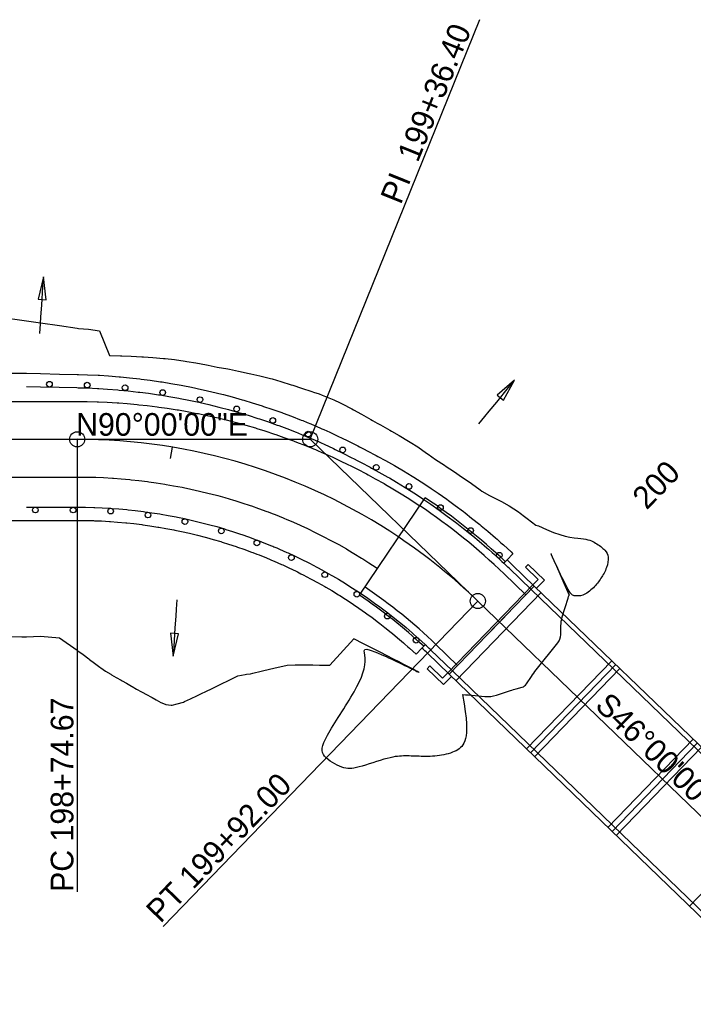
# Model space of a CAD drawing. Extents: x 1556849 to 1559393, y 1802592 to 1804749.
# Drawn here: x 1558175.4 to 1558353.8, y 1804489.1 to 1804749.2 of the extents above; entities that cross this region are included whole.
import ezdxf

# ---------------------------------------------------------------- set-up
doc = ezdxf.new("R2010")
doc.units = 0
for name, color, linetype in [('B_Concrete', 7, 'Continuous'), ('B_Concrete hidden', 7, 'Continuous'), ('R_Horz Alg', 7, 'Continuous'), ('R_Horz Alg Annot', 7, 'Continuous'), ('R_Proposed Const Limits_Cut', 7, 'Continuous'), ('R_Proposed Const Limits_Fill', 7, 'Continuous'), ('R_Proposed Road_Lane', 7, 'Continuous'), ('R_Proposed Road_Shoulder', 7, 'Continuous'), ('R_Steel', 7, 'Continuous'), ('R_Water', 7, 'Continuous')]:
    doc.layers.add(name, color=color, linetype=linetype)

msp = doc.modelspace()

# ---------------------------------------------------------------- linework, layer by layer
at = {"layer": 'B_Concrete'}
for p, q in [((1558265.41, 1804596.53), (1558282.78, 1804622.41)), ((1558303.63, 1804605.02), (1558304.49, 1804605.93)), ((1558305.08, 1804603.64), (1558310.83, 1804598.09)), ((1558305.95, 1804604.54), (1558311.7, 1804598.99)), ((1558309.35, 1804603.98), (1558310.04, 1804604.7)), ((1558312.7, 1804600.74), (1558309.35, 1804603.98)), ((1558314.36, 1804600.53), (1558310.04, 1804604.7)), ((1558303.69, 1804602.21), (1558309.44, 1804596.65)), ((1558311.34, 1804599.33), (1558312.7, 1804600.74)), ((1558312.3, 1804598.41), (1558314.36, 1804600.53)), ((1558289.13, 1804575.61), (1558311.7, 1804598.99)), ((1558310.83, 1804598.09), (1558397.15, 1804514.73)), ((1558311.7, 1804598.99), (1558398.02, 1804515.63)), ((1558281.93, 1804582.53), (1558282.79, 1804583.44)), ((1558284.24, 1804582.06), (1558289.99, 1804576.51)), ((1558285.63, 1804583.5), (1558291.38, 1804577.95)), ((1558283.37, 1804581.16), (1558289.13, 1804575.61)), ((1558284.05, 1804577.79), (1558283.35, 1804577.07)), ((1558287.67, 1804572.9), (1558283.35, 1804577.07)), ((1558287.4, 1804574.55), (1558284.05, 1804577.79)), ((1558289.99, 1804576.51), (1558376.31, 1804493.15)), ((1558310.71, 1804554.77), (1558333.28, 1804578.15)), ((1558288.77, 1804575.95), (1558287.4, 1804574.55)), ((1558289.72, 1804575.03), (1558287.67, 1804572.9)), ((1558289.13, 1804575.61), (1558375.45, 1804492.25)), ((1558332.29, 1804533.93), (1558354.86, 1804557.31))]:
    msp.add_line(p, q, dxfattribs=at)
for radius, start, end in [(165.37, 46.6954, 56.125), (162.79, 46, 56.125), (164.79, 46, 46.6954), (166.04, 46, 46.6954), (136.79, 46, 56.125), (134.21, 46.8501, 56.125), (133.54, 46, 46.8501), (134.79, 46, 46.8501)]:
    msp.add_arc((1558190.61, 1804485.1), radius, start, end, dxfattribs=at)
at = {"layer": 'B_Concrete hidden'}
for p, q in [((1558288.77, 1804575.95), (1558311.34, 1804599.33)), ((1558290.92, 1804573.87), (1558313.5, 1804597.25)), ((1558309.63, 1804555.81), (1558332.2, 1804579.19)), ((1558311.78, 1804553.73), (1558334.36, 1804577.1)), ((1558331.21, 1804534.97), (1558353.78, 1804558.35)), ((1558333.36, 1804532.89), (1558355.94, 1804556.26)), ((1558352.79, 1804514.13), (1558375.36, 1804537.51))]:
    msp.add_line(p, q, dxfattribs=at)
at = {"layer": 'R_Horz Alg'}
for p, q in [((1558133.23, 1804637.89), (1558190.61, 1804637.89)), ((1558296.74, 1804595.01), (1558406.38, 1804489.14))]:
    msp.add_line(p, q, dxfattribs=at)
for start, end in [(56.125, 90), (46, 56.125)]:
    msp.add_arc((1558190.61, 1804485.1), 152.79, start, end, dxfattribs=at)
at = {"layer": 'R_Horz Alg Annot'}
for p, q in [((1558190.61, 1804637.89), (1558252.34, 1804637.89)), ((1558252.34, 1804637.89), (1558296.74, 1804595.01))]:
    msp.add_line(p, q, dxfattribs=at)
for points in [[(1558252.34, 1804637.89), (1558297.29, 1804749.16)], [(1558190.61, 1804637.89), (1558190.61, 1804517.89)], [(1558215.33, 1804632.84), (1558215.82, 1804635.8)], [(1558296.74, 1804595.01), (1558213.38, 1804508.69)], [(1558305.28, 1804592.33), (1558299.72, 1804586.58)]]:
    msp.add_lwpolyline(points, dxfattribs=at)
for centre in [(1558190.61, 1804637.89), (1558252.34, 1804637.89), (1558296.74, 1804595.01)]:
    msp.add_circle(centre, 2, dxfattribs=at)
at = {"layer": 'R_Proposed Const Limits_Cut'}
for points in [[(1558084.62, 1804651.59), (1558134.19, 1804674.62), (1558135.94, 1804674.03), (1558140.94, 1804673.91), (1558145.94, 1804672.74), (1558150.94, 1804669.51), (1558155.94, 1804668.74), (1558160.94, 1804668.97), (1558165.94, 1804669.71), (1558167.19, 1804669.89), (1558170.5, 1804670.29), (1558170.94, 1804670.22), (1558175.94, 1804669.48), (1558177.19, 1804669.3), (1558180.94, 1804668.76), (1558185.94, 1804668.03), (1558190.61, 1804667.36), (1558191, 1804667.3), (1558193.58, 1804667.1), (1558196.54, 1804666.69), (1558199.19, 1804660.12)], [(1558292.7, 1804570.21), (1558293.43, 1804570.18), (1558294.27, 1804570.12), (1558295.12, 1804570.05), (1558298.61, 1804569.72), (1558299.39, 1804569.68), (1558300.16, 1804569.73), (1558300.92, 1804569.85), (1558301.67, 1804570.06), (1558305.39, 1804571.28), (1558305.77, 1804571.4), (1558306.15, 1804571.52), (1558306.53, 1804571.63), (1558306.91, 1804571.74), (1558308.44, 1804572.16), (1558308.81, 1804572.3), (1558309.13, 1804572.49), (1558309.4, 1804572.74), (1558309.64, 1804573.04), (1558310.93, 1804575.04), (1558311.22, 1804575.48), (1558311.53, 1804575.92), (1558311.84, 1804576.34), (1558312.17, 1804576.76), (1558317.92, 1804583.94), (1558318.25, 1804584.42), (1558318.48, 1804584.94), (1558318.63, 1804585.49), (1558318.69, 1804586.07), (1558318.73, 1804588.46), (1558318.77, 1804589.06), (1558318.84, 1804589.65), (1558318.95, 1804590.23), (1558319.11, 1804590.81), (1558320.65, 1804595.77), (1558320.79, 1804596.21), (1558320.92, 1804596.59)], [(1558170.94, 1804585.64), (1558175.94, 1804585.5), (1558177.19, 1804585.55), (1558180.94, 1804585.7), (1558185.94, 1804585.24), (1558190.61, 1804581.97), (1558190.82, 1804581.82), (1558192.17, 1804580.81), (1558193.7, 1804579.67), (1558193.9, 1804579.52), (1558195.19, 1804578.55), (1558196.65, 1804577.45), (1558196.85, 1804577.3), (1558198.08, 1804576.39), (1558199.5, 1804575.58), (1558199.71, 1804575.47), (1558200.91, 1804574.78), (1558202.29, 1804573.99), (1558202.49, 1804573.87), (1558203.66, 1804573.2), (1558205, 1804572.43), (1558205.2, 1804572.32), (1558206.33, 1804571.67), (1558207.66, 1804570.94), (1558207.85, 1804570.83), (1558208.96, 1804570.22), (1558210.26, 1804569.51), (1558210.45, 1804569.4), (1558211.54, 1804568.8), (1558212.81, 1804568.09), (1558213.01, 1804567.98), (1558214.13, 1804567.62), (1558215.55, 1804567.44), (1558215.77, 1804567.41), (1558217.12, 1804567.75), (1558218.78, 1804568.22), (1558219.07, 1804568.36), (1558220.61, 1804569.09), (1558222.51, 1804569.99), (1558222.83, 1804570.15), (1558223.74, 1804570.59), (1558224.47, 1804570.94), (1558226.51, 1804571.92), (1558226.86, 1804572.09), (1558227.28, 1804572.3), (1558227.92, 1804572.61), (1558228.63, 1804572.95), (1558230.83, 1804574.03), (1558231.22, 1804574.22), (1558233.13, 1804575.15), (1558235.15, 1804575.57), (1558235.48, 1804575.6), (1558236.48, 1804575.74), (1558237.17, 1804575.9), (1558239.32, 1804576.4), (1558239.71, 1804576.49), (1558241.55, 1804576.92), (1558243.84, 1804577.47), (1558244.26, 1804577.57), (1558246.21, 1804578.04), (1558248.33, 1804578.1), (1558248.71, 1804578.09), (1558250.45, 1804578.08), (1558252.61, 1804578.06), (1558253.01, 1804578.06), (1558254.82, 1804578.05), (1558257.08, 1804578.04), (1558257.51, 1804578.04), (1558263.88, 1804585.03)]]:
    msp.add_lwpolyline(points, dxfattribs=at)
at = {"layer": 'R_Proposed Const Limits_Fill'}
msp.add_lwpolyline([(1558199.19, 1804660.12), (1558202.06, 1804660.05), (1558202.46, 1804660.03), (1558204.92, 1804659.93), (1558207.78, 1804659.77), (1558208.19, 1804659.74), (1558210.65, 1804659.56), (1558213.51, 1804659.31), (1558213.92, 1804659.27), (1558216.37, 1804659.01), (1558219.21, 1804658.63), (1558219.63, 1804658.56), (1558222.04, 1804658.13), (1558224.87, 1804657.59), (1558225.29, 1804657.51), (1558227.69, 1804657.05), (1558230.52, 1804656.54), (1558230.95, 1804656.45), (1558233.34, 1804655.98), (1558236.16, 1804655.37), (1558236.6, 1804655.28), (1558238.97, 1804654.73), (1558241.78, 1804654.04), (1558242.22, 1804653.92), (1558244.55, 1804653.24), (1558247.29, 1804652.34), (1558247.74, 1804652.2), (1558250.04, 1804651.48), (1558252.79, 1804650.57), (1558253.24, 1804650.42), (1558254.7, 1804649.91), (1558255.51, 1804649.59), (1558258.18, 1804648.51), (1558258.63, 1804648.32), (1558258.98, 1804648.17), (1558259.95, 1804647.72), (1558260.81, 1804647.3), (1558263.36, 1804645.93), (1558263.79, 1804645.68), (1558265.89, 1804644.53), (1558268.42, 1804643.15), (1558268.85, 1804642.9), (1558270.11, 1804642.19), (1558270.93, 1804641.74), (1558273.44, 1804640.33), (1558273.88, 1804640.08), (1558275.93, 1804638.89), (1558278.39, 1804637.42), (1558278.83, 1804637.15), (1558280.83, 1804635.89), (1558283.17, 1804634.22), (1558283.59, 1804633.91), (1558285.49, 1804632.52), (1558287.9, 1804630.99), (1558288.35, 1804630.7), (1558290.3, 1804629.41), (1558292.67, 1804627.8), (1558293.11, 1804627.5), (1558295.02, 1804626.16), (1558297.34, 1804624.48), (1558297.78, 1804624.15), (1558299.85, 1804623.02), (1558302.45, 1804621.66), (1558302.96, 1804621.4), (1558305.05, 1804620.26), (1558307.52, 1804618.69), (1558307.96, 1804618.33), (1558309.08, 1804617.41), (1558309.77, 1804616.86), (1558312.12, 1804615.13), (1558312.79, 1804614.99)], dxfattribs=at)
for points in [[(1558312.79, 1804614.99), (1558318.79, 1804611.9), (1558325.13, 1804611.76), (1558327.95, 1804610.54), (1558330.71, 1804608.38), (1558331.48, 1804606.9), (1558331.03, 1804603.84), (1558329.34, 1804600.99), (1558327.57, 1804598.53), (1558324.43, 1804596.13), (1558322.07, 1804596.46), (1558320.92, 1804596.59), (1558312.79, 1804614.99), (1558320.92, 1804596.59)], [(1558292.7, 1804570.21), (1558293.96, 1804563.22), (1558293.84, 1804557.49), (1558291.35, 1804555.19), (1558286.58, 1804553.8), (1558281.58, 1804553.8), (1558277.55, 1804554.01), (1558273.57, 1804553.81), (1558264.24, 1804550.49), (1558261.18, 1804550.4), (1558255.09, 1804553.8), (1558255.32, 1804557.76), (1558265.09, 1804571.88), (1558268.12, 1804580.53), (1558263.88, 1804585.03), (1558292.7, 1804570.21), (1558263.88, 1804585.03)]]:
    msp.add_open_spline(points, degree=3, dxfattribs=at)
at = {"layer": 'R_Proposed Road_Lane'}
for points in [[(1558170.94, 1804647.89), (1558175.94, 1804647.89), (1558177.19, 1804647.89), (1558180.94, 1804647.89), (1558185.94, 1804647.89), (1558190.61, 1804647.89), (1558190.96, 1804647.89), (1558193.27, 1804647.87), (1558195.93, 1804647.81), (1558196.29, 1804647.79), (1558198.58, 1804647.7), (1558201.24, 1804647.55), (1558201.61, 1804647.52), (1558203.89, 1804647.35), (1558206.54, 1804647.11), (1558206.92, 1804647.07), (1558209.18, 1804646.83), (1558211.82, 1804646.5), (1558212.21, 1804646.45), (1558214.46, 1804646.14), (1558217.09, 1804645.73), (1558217.47, 1804645.66), (1558219.71, 1804645.27), (1558222.32, 1804644.77), (1558222.71, 1804644.7), (1558224.93, 1804644.23), (1558227.52, 1804643.65), (1558227.92, 1804643.56), (1558230.11, 1804643.03), (1558232.68, 1804642.36), (1558233.08, 1804642.25), (1558235.24, 1804641.65), (1558237.8, 1804640.9), (1558238.2, 1804640.78), (1558240.34, 1804640.11), (1558242.86, 1804639.28), (1558243.27, 1804639.14), (1558245.37, 1804638.4), (1558247.87, 1804637.49), (1558248.28, 1804637.33), (1558249.45, 1804636.89), (1558250.35, 1804636.53), (1558252.82, 1804635.54), (1558253.23, 1804635.37), (1558253.72, 1804635.16), (1558254.46, 1804634.85), (1558255.27, 1804634.5), (1558257.7, 1804633.42), (1558258.11, 1804633.24), (1558260.12, 1804632.31), (1558262.51, 1804631.15), (1558262.92, 1804630.95), (1558264.12, 1804630.35), (1558264.89, 1804629.96), (1558267.24, 1804628.73), (1558267.66, 1804628.5), (1558269.58, 1804627.45), (1558271.9, 1804626.14), (1558272.31, 1804625.91), (1558274.19, 1804624.8), (1558276.46, 1804623.41), (1558276.87, 1804623.16), (1558278.71, 1804621.99), (1558280.93, 1804620.53), (1558281.34, 1804620.26)], [(1558170.94, 1804627.89), (1558175.94, 1804627.89), (1558177.19, 1804627.89), (1558180.94, 1804627.89), (1558185.94, 1804627.89), (1558190.61, 1804627.89), (1558190.92, 1804627.89), (1558192.94, 1804627.87), (1558195.27, 1804627.82), (1558195.59, 1804627.81), (1558197.6, 1804627.72), (1558199.93, 1804627.59), (1558200.26, 1804627.57), (1558202.26, 1804627.42), (1558204.58, 1804627.21), (1558204.91, 1804627.18), (1558206.9, 1804626.96), (1558209.22, 1804626.68), (1558209.55, 1804626.63), (1558211.53, 1804626.35), (1558213.83, 1804625.99), (1558214.17, 1804625.94), (1558216.13, 1804625.59), (1558218.42, 1804625.16), (1558218.77, 1804625.09), (1558220.71, 1804624.68), (1558222.99, 1804624.17), (1558223.33, 1804624.09), (1558225.25, 1804623.63), (1558227.51, 1804623.04), (1558227.86, 1804622.95), (1558229.76, 1804622.42), (1558232, 1804621.76), (1558232.35, 1804621.65), (1558234.23, 1804621.07), (1558236.44, 1804620.34), (1558236.8, 1804620.22), (1558238.65, 1804619.57), (1558240.84, 1804618.77), (1558241.2, 1804618.63), (1558242.22, 1804618.24), (1558243.01, 1804617.93), (1558245.18, 1804617.05), (1558245.54, 1804616.9), (1558245.97, 1804616.72), (1558246.61, 1804616.45), (1558247.32, 1804616.15), (1558249.46, 1804615.2), (1558249.82, 1804615.04), (1558251.58, 1804614.22), (1558253.68, 1804613.21), (1558254.04, 1804613.03), (1558255.08, 1804612.51), (1558255.76, 1804612.16), (1558257.83, 1804611.08), (1558258.19, 1804610.89), (1558259.88, 1804609.96), (1558261.91, 1804608.82), (1558262.27, 1804608.61), (1558263.92, 1804607.63), (1558265.91, 1804606.42), (1558266.27, 1804606.2), (1558267.88, 1804605.17), (1558269.84, 1804603.9), (1558270.19, 1804603.66), (1558270.19, 1804603.66)]]:
    msp.add_lwpolyline(points, dxfattribs=at)
at = {"layer": 'R_Proposed Road_Shoulder'}
for points in [[(1558170.94, 1804655.39), (1558175.94, 1804655.39), (1558177.19, 1804655.39), (1558180.94, 1804655.31), (1558185.94, 1804655.19), (1558190.61, 1804655.08), (1558190.98, 1804655.07), (1558193.38, 1804655), (1558196.16, 1804654.87), (1558196.53, 1804654.85), (1558198.93, 1804654.7), (1558201.69, 1804654.48), (1558202.08, 1804654.45), (1558204.45, 1804654.22), (1558207.21, 1804653.91), (1558207.6, 1804653.86), (1558209.96, 1804653.56), (1558212.7, 1804653.16), (1558213.1, 1804653.1), (1558215.43, 1804652.72), (1558218.16, 1804652.23), (1558218.56, 1804652.16), (1558220.88, 1804651.7), (1558223.58, 1804651.13), (1558223.99, 1804651.04), (1558226.28, 1804650.51), (1558228.96, 1804649.85), (1558229.37, 1804649.74), (1558231.64, 1804649.14), (1558234.29, 1804648.39), (1558234.71, 1804648.27), (1558236.94, 1804647.6), (1558239.57, 1804646.77), (1558239.99, 1804646.63), (1558242.19, 1804645.89), (1558244.79, 1804644.97), (1558245.21, 1804644.82), (1558247.38, 1804644.01), (1558249.94, 1804643), (1558250.37, 1804642.84), (1558251.56, 1804642.35), (1558252.49, 1804641.96), (1558255.03, 1804640.87), (1558255.45, 1804640.69), (1558255.95, 1804640.46), (1558256.71, 1804640.12), (1558257.54, 1804639.75), (1558260.03, 1804638.58), (1558260.46, 1804638.37), (1558262.51, 1804637.37), (1558264.96, 1804636.12), (1558265.38, 1804635.9), (1558266.6, 1804635.26), (1558267.4, 1804634.85), (1558269.83, 1804633.58), (1558270.26, 1804633.35), (1558272.25, 1804632.26), (1558274.64, 1804630.91), (1558275.07, 1804630.66), (1558277.01, 1804629.52), (1558279.36, 1804628.09), (1558279.79, 1804627.82), (1558281.69, 1804626.62), (1558283.99, 1804625.11), (1558284.41, 1804624.83), (1558286.26, 1804623.57), (1558288.51, 1804621.98), (1558288.93, 1804621.68), (1558290.73, 1804620.37), (1558292.93, 1804618.71), (1558293.35, 1804618.39), (1558295.1, 1804617.02), (1558297.24, 1804615.3), (1558297.65, 1804614.96), (1558299.35, 1804613.54), (1558301.44, 1804611.74), (1558301.84, 1804611.39), (1558302.87, 1804610.47), (1558303.49, 1804609.92), (1558305.52, 1804608.06), (1558306.03, 1804607.57)], [(1558170.94, 1804616.39), (1558175.92, 1804616.39), (1558175.94, 1804616.39), (1558177.19, 1804616.39), (1558180.94, 1804616.39), (1558185.94, 1804616.39), (1558190.61, 1804616.39), (1558190.89, 1804616.39), (1558192.75, 1804616.38), (1558194.9, 1804616.32), (1558195.19, 1804616.31), (1558197.04, 1804616.24), (1558199.18, 1804616.11), (1558199.48, 1804616.09), (1558201.32, 1804615.96), (1558203.46, 1804615.76), (1558203.76, 1804615.73), (1558205.59, 1804615.54), (1558207.72, 1804615.27), (1558208.03, 1804615.23), (1558209.84, 1804614.98), (1558211.96, 1804614.64), (1558212.28, 1804614.59), (1558214.08, 1804614.28), (1558216.18, 1804613.88), (1558216.5, 1804613.81), (1558218.28, 1804613.44), (1558220.38, 1804612.97), (1558220.7, 1804612.9), (1558222.46, 1804612.47), (1558224.54, 1804611.93), (1558224.86, 1804611.85), (1558226.61, 1804611.36), (1558228.67, 1804610.76), (1558228.99, 1804610.66), (1558230.71, 1804610.12), (1558232.75, 1804609.45), (1558233.08, 1804609.33), (1558234.78, 1804608.74), (1558236.79, 1804608), (1558237.12, 1804607.88), (1558238.2, 1804607.46), (1558238.79, 1804607.23), (1558240.78, 1804606.43), (1558241.11, 1804606.29), (1558241.37, 1804606.18), (1558242.1, 1804605.87), (1558242.76, 1804605.59), (1558244.72, 1804604.72), (1558245.05, 1804604.57), (1558246.67, 1804603.82), (1558248.6, 1804602.89), (1558248.93, 1804602.73), (1558249.89, 1804602.25), (1558250.51, 1804601.93), (1558252.41, 1804600.93), (1558252.75, 1804600.76), (1558254.3, 1804599.91), (1558256.17, 1804598.85), (1558256.5, 1804598.66), (1558258.02, 1804597.77), (1558259.85, 1804596.65), (1558260.18, 1804596.44), (1558261.66, 1804595.5), (1558263.46, 1804594.33), (1558263.78, 1804594.11), (1558265.23, 1804593.12), (1558266.99, 1804591.89), (1558267.31, 1804591.66), (1558268.72, 1804590.63), (1558270.43, 1804589.34), (1558270.76, 1804589.09), (1558272.13, 1804588.02), (1558273.8, 1804586.67), (1558274.12, 1804586.41), (1558275.44, 1804585.3), (1558277.07, 1804583.9), (1558277.39, 1804583.62), (1558278.19, 1804582.91), (1558278.67, 1804582.48), (1558280.4, 1804580.89)], [(1558306.03, 1804607.57), (1558304.49, 1804605.93)], [(1558280.4, 1804580.89), (1558281.93, 1804582.53)]]:
    msp.add_lwpolyline(points, dxfattribs=at)
at = {"layer": 'R_Steel'}
for points in [[(1558177.19, 1804651.89), (1558180.86, 1804651.81), (1558185.86, 1804651.69), (1558190.53, 1804651.58), (1558190.89, 1804651.57), (1558193.25, 1804651.5), (1558195.98, 1804651.37), (1558196.33, 1804651.35), (1558198.68, 1804651.21), (1558201.4, 1804650.99), (1558201.76, 1804650.96), (1558204.09, 1804650.74), (1558206.8, 1804650.43), (1558207.17, 1804650.39), (1558209.48, 1804650.09), (1558212.18, 1804649.7), (1558212.55, 1804649.64), (1558214.85, 1804649.27), (1558217.53, 1804648.79), (1558217.9, 1804648.72), (1558220.18, 1804648.27), (1558222.84, 1804647.71), (1558223.22, 1804647.63), (1558225.47, 1804647.11), (1558228.11, 1804646.45), (1558228.49, 1804646.36), (1558230.71, 1804645.77), (1558233.33, 1804645.03), (1558233.71, 1804644.92), (1558235.91, 1804644.26), (1558238.5, 1804643.44), (1558238.89, 1804643.31), (1558241.05, 1804642.58), (1558243.61, 1804641.68), (1558244, 1804641.53), (1558246.13, 1804640.74), (1558248.65, 1804639.75), (1558249.05, 1804639.59), (1558250.23, 1804639.11), (1558251.13, 1804638.74), (1558253.63, 1804637.66), (1558254.03, 1804637.49), (1558254.53, 1804637.27), (1558255.27, 1804636.93), (1558256.07, 1804636.57), (1558258.53, 1804635.42), (1558258.93, 1804635.23), (1558260.94, 1804634.24), (1558263.36, 1804633.01), (1558263.76, 1804632.8), (1558264.99, 1804632.15), (1558265.79, 1804631.74), (1558268.2, 1804630.48), (1558268.6, 1804630.27), (1558270.55, 1804629.2), (1558272.91, 1804627.87), (1558273.3, 1804627.64), (1558275.21, 1804626.51), (1558277.53, 1804625.11), (1558277.92, 1804624.86), (1558279.79, 1804623.68), (1558282.05, 1804622.19), (1558282.45, 1804621.93), (1558284.27, 1804620.69), (1558286.48, 1804619.13), (1558286.88, 1804618.85), (1558288.65, 1804617.55), (1558290.81, 1804615.93), (1558291.2, 1804615.63), (1558292.92, 1804614.28), (1558295.03, 1804612.58), (1558295.42, 1804612.27), (1558297.09, 1804610.87), (1558299.14, 1804609.1), (1558299.53, 1804608.77), (1558300.54, 1804607.87), (1558301.14, 1804607.33), (1558303.13, 1804605.49), (1558303.64, 1804605.02)], [(1558177.19, 1804619.89), (1558180.94, 1804619.89), (1558185.94, 1804619.89), (1558190.61, 1804619.89), (1558190.91, 1804619.89), (1558192.81, 1804619.88), (1558195, 1804619.82), (1558195.32, 1804619.81), (1558197.21, 1804619.73), (1558199.4, 1804619.61), (1558199.73, 1804619.58), (1558201.61, 1804619.44), (1558203.79, 1804619.25), (1558204.12, 1804619.21), (1558205.99, 1804619.01), (1558208.16, 1804618.75), (1558208.5, 1804618.7), (1558210.36, 1804618.44), (1558212.52, 1804618.1), (1558212.86, 1804618.04), (1558214.7, 1804617.72), (1558216.85, 1804617.31), (1558217.2, 1804617.24), (1558219.02, 1804616.86), (1558221.16, 1804616.39), (1558221.51, 1804616.3), (1558223.31, 1804615.87), (1558225.43, 1804615.32), (1558225.79, 1804615.22), (1558227.57, 1804614.73), (1558229.67, 1804614.11), (1558230.02, 1804614), (1558231.78, 1804613.45), (1558233.86, 1804612.76), (1558234.22, 1804612.64), (1558235.96, 1804612.04), (1558238.01, 1804611.28), (1558238.37, 1804611.15), (1558239.46, 1804610.73), (1558240.09, 1804610.48), (1558242.11, 1804609.67), (1558242.46, 1804609.52), (1558242.73, 1804609.41), (1558243.48, 1804609.09), (1558244.16, 1804608.8), (1558246.15, 1804607.92), (1558246.51, 1804607.75), (1558248.16, 1804606.99), (1558250.13, 1804606.04), (1558250.49, 1804605.86), (1558251.47, 1804605.37), (1558252.12, 1804605.04), (1558254.05, 1804604.03), (1558254.41, 1804603.83), (1558256, 1804602.97), (1558257.9, 1804601.89), (1558258.26, 1804601.68), (1558259.82, 1804600.77), (1558261.68, 1804599.63), (1558262.04, 1804599.41), (1558263.56, 1804598.45), (1558265.39, 1804597.25), (1558265.74, 1804597.01), (1558267.22, 1804596), (1558269.01, 1804594.74), (1558269.36, 1804594.49), (1558270.8, 1804593.44), (1558272.55, 1804592.12), (1558272.9, 1804591.86), (1558274.3, 1804590.76), (1558276.01, 1804589.39), (1558276.35, 1804589.11), (1558277.71, 1804587.97), (1558279.37, 1804586.54), (1558279.7, 1804586.25), (1558280.52, 1804585.52), (1558281.03, 1804585.06), (1558282.77, 1804583.47)]]:
    msp.add_lwpolyline(points, dxfattribs=at)
for centre in [(1558183.27, 1804652.5), (1558193.27, 1804652.25), (1558203.3, 1804651.57), (1558213.26, 1804650.29), (1558223.13, 1804648.41), (1558232.86, 1804645.94), (1558242.43, 1804642.89), (1558251.8, 1804639.26), (1558260.93, 1804635.08), (1558269.83, 1804630.45), (1558278.5, 1804625.38), (1558179.54, 1804619.14), (1558189.54, 1804619.14), (1558199.48, 1804618.85), (1558209.37, 1804617.82), (1558286.84, 1804619.8), (1558219.15, 1804616.07), (1558228.79, 1804613.59), (1558294.83, 1804613.71), (1558238.2, 1804610.41), (1558302.44, 1804607.15), (1558247.36, 1804606.53), (1558256.2, 1804601.99), (1558264.69, 1804596.81), (1558272.76, 1804591.01), (1558280.39, 1804584.63)]:
    msp.add_circle(centre, 0.75, dxfattribs=at)
at = {"layer": 'R_Water'}
for p, q in [((1558181.73, 1804680.93), (1558180.26, 1804675.02)), ((1558182.37, 1804674.87), (1558181.73, 1804680.93)), ((1558180.26, 1804675.02), (1558182.37, 1804674.87)), ((1558306.49, 1804653.55), (1558301.86, 1804649.58)), ((1558303.5, 1804648.24), (1558306.49, 1804653.55)), ((1558301.86, 1804649.58), (1558303.5, 1804648.24)), ((1558217.47, 1804586.31), (1558215.36, 1804586.45)), ((1558215.36, 1804586.45), (1558216, 1804580.39)), ((1558216, 1804580.39), (1558217.47, 1804586.31))]:
    msp.add_line(p, q, dxfattribs=at)
for points in [[(1558180.7, 1804665.97), (1558180.87, 1804668.48), (1558181, 1804670.36), (1558181.21, 1804673.45), (1558181.55, 1804678.42), (1558181.73, 1804680.93)], [(1558296.97, 1804641.95), (1558298.57, 1804643.9), (1558299.76, 1804645.36), (1558301.73, 1804647.75), (1558304.89, 1804651.6), (1558306.49, 1804653.55)], [(1558217.03, 1804595.36), (1558216.86, 1804592.85), (1558216.73, 1804590.97), (1558216.52, 1804587.87), (1558216.18, 1804582.9), (1558216, 1804580.39)]]:
    msp.add_lwpolyline(points, dxfattribs=at)

# ---------------------------------------------------------------- texts
at = {"layer": 'R_Horz Alg Annot'}
for s, rotation, p in [('PI  199+36.40', 68, (1558276.31, 1804699.9)), ('N90%%d00\'00"E', 360, (1558190.33, 1804638.84)), ('200', 46, (1558341.45, 1804618.98)), ('PC 198+74.67', 90, (1558189.61, 1804517.89)), ('S46%%d00\'00"E', 316, (1558327.47, 1804566.92)), ('PT 199+92.00', 46, (1558212.66, 1804509.39))]:
    msp.add_text(s, height=6, rotation=rotation, dxfattribs=at).set_placement(p)

doc.saveas('drawing.dxf')
